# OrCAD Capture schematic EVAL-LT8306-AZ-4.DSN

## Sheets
1 P2 misc
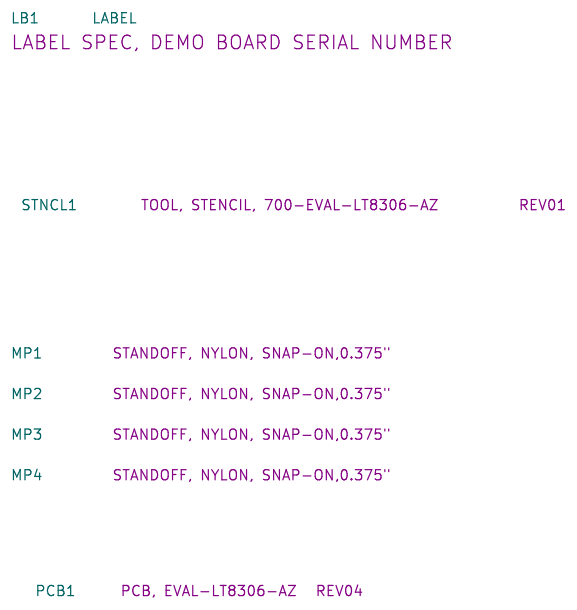
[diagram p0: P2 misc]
2 P1: size Custom; note: LOW-IQ NO-OPTO ISOLATED FLYBACK CONTROLLER
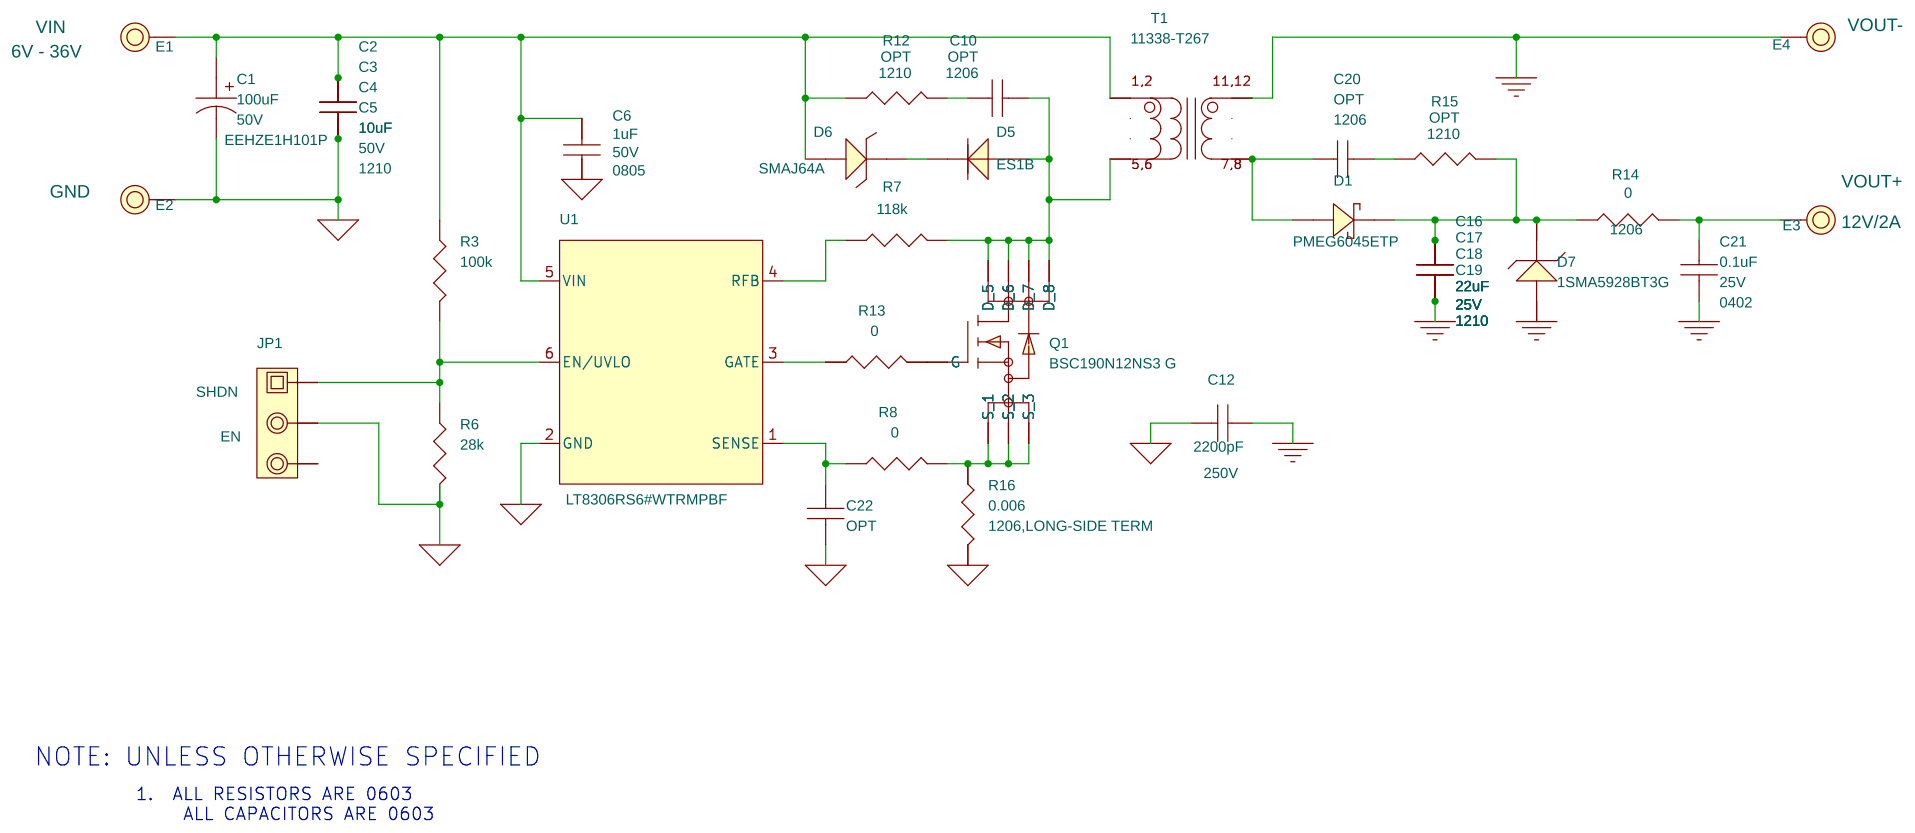
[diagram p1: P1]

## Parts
sheet P1
C1  100uF  [PANASONIC_ZE_10X10-2]
C2  10uF  [CC1210N]
C3  10uF  [CC1210N]
C4  10uF  [CC1210N]
C5  10uF  [CC1210N]
C6  1uF  [CC0805N]
C10  OPT  [CC1206N]
C12  2200pF  [CC1812N]
C16  22uF  [CC1210N]
C17  22uF  [CC1210N]
C18  22uF  [CC1210N]
C19  22uF  [CC1210N]
C20  OPT  [CC1206N]
C21  0.1uF  [CC0402N]
C22  OPT  [CC0603N]
D1  PMEG6045ETP  [SOD-128N]
D5  ES1B  [SMA-N]
D6  SMAJ64A  [SMA-N]
D7  1SMA5928BT3G  [SMA-N]
E1  TEST POINT  [MILLMAX2501]
E2  TEST POINT  [MILLMAX2501]
E3  TEST POINT  [MILLMAX2501]
E4  TEST POINT  [MILLMAX2501]
JP1  HDR  [HD1X3-079]
Q1  BSC190N12NS3 G  [INFINEON-PG-TDSON-8]
R3  100k  [CR0603N]
R6  28k  [CR0603N]
R7  118k  [CR0603N]
R8  0  [CR0603N]
R12  OPT  [CR1210N]
R13  0  [CR0603N]
R14  0  [CR1206N]
R15  OPT  [CR1210N]
R16  0.006  [SUSUMU-KRL3216]
T1  11338-T267  [SUMIDA-CEEH178]
U1  LT8306RS6#WTRMPBF  [LTC-S6-6-1636]
XJP1  SHUNT
sheet P2 misc
LB1  LABEL  [895-0154_REV01]
MP1  STANDOFF, NYLON, SNAP-ON  [KEYSTONE_8829-8834]
MP2  STANDOFF, NYLON, SNAP-ON  [KEYSTONE_8829-8834]
MP3  STANDOFF, NYLON, SNAP-ON  [KEYSTONE_8829-8834]
MP4  STANDOFF, NYLON, SNAP-ON  [KEYSTONE_8829-8834]
PCB1  PCB, EVAL-LT8306-AZ
STNCL1  TOOL, STENCIL, 700-EVAL-LT8306-AZ

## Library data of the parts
C1 = CAP_P_ALT: CAP.,100uF,ALUM POLY,50V,20%,10mmX10.2mm,AEC-Q200; CLASS: DISCRETE; Dielectric Type: ALUM POLY; Inventory Qty: 0; Manufacturer: PANASONIC; Manufacturer PN: EEHZE1H101P; PART_NUMBER: 150-0875; Package Size: 10mmX10.2mm; Rated Voltage: 50V; Tolerance: 20%
C2-C5 = CAP: CAP.,10uF,X5R,50V,10%,1210; CLASS: DISCRETE; Dielectric Type: X5R; FPLIST: CC1210N,CC1210L,CC1210M; Inventory Qty: 14956; Manufacturer: TDK; Manufacturer PN: C3225X5R1H106K250AB; PART_NUMBER: 150-3288; Package Size: 1210; Rated Voltage: 50V; Tolerance: 10%
C6 = CAP: CAP.,1uF,X7R,50V,10%,0805; CLASS: DISCRETE; Dielectric Type: X7R; FPLIST: CC0805N,CC0805L,CC0805M; Inventory Qty: 31167; Manufacturer: TAIYO YUDEN; Manufacturer PN: UMK212B7105KG-T; PART_NUMBER: 150-3335; Package Size: 0805; Rated Voltage: 50V; Tolerance: 10%
C10 C20 = CAP: CAP., OPTION, 1206; CLASS: DISCRETE; FPLIST: CC1206N,CC1206L,CC1206M; PART_NUMBER: 150-3160; Package Size: 1206; Package Type: SMD
C12 = CAP: CAP.,2200pF,X7R,250V,10%,1812; CLASS: DISCRETE; Dielectric Type: X7R; FPLIST: CC1812N,CC1812L,CC1812M; Inventory Qty: 6450; Manufacturer: MURATA; Manufacturer PN: GA343QR7GD222KW01L; PART_NUMBER: 150-0105; Package Size: 1812; Rated Voltage: 250V; Tolerance: 10%
C16-C19 = CAP: CAP.,22uF,X7R,25V,10%,1210; CLASS: DISCRETE; Dielectric Type: X7R; FPLIST: CC1210N,CC1210L,CC1210M; Inventory Qty: 28580; Manufacturer: AVX; Manufacturer PN: 12103C226KAT2A; PART_NUMBER: 150-3343; Package Size: 1210; Rated Voltage: 25V; Tolerance: 10%
C21 = CAP: CAP.,0.1uF,X7R,25V,10%,0402; CLASS: DISCRETE; Dielectric Type: X7R; FPLIST: CC0402N,CC0402L,CC0402M; Inventory Qty: 44848; Manufacturer: AVX; Manufacturer PN: 04023C104KAT2A; PART_NUMBER: 150-2276; Package Size: 0402; Rated Voltage: 25V; Tolerance: 10%
C22 = CAP: CAP., OPTION, 0603; CLASS: DISCRETE; FPLIST: CC0603N,CC0603L,CC0603M; PART_NUMBER: 150-3038; Package Size: 0603; Package Type: SMD
D1 = DIODE_SCHOTTKY_A_ALT: DIODE,SCHOTTKY,60V,4.5A,SOD-128,AEC-Q101; CLASS: DISCRETE; FPLIST: SOD-128N,SOD-128L,SOD-128M; Inventory Qty: 0; Manufacturer: NEXPERIA; Manufacturer PN: PMEG6045ETPX; Max Forward Current or Rated Power: 4.5A; PART_NUMBER: 210-0577; Package Size: SOD-128; Package Type: SOD-128; Rated Voltage or Zener Voltage: 60V
D5 = DIODE_A_ALT: DIODE,SWITCHING,100V,1A,2-pin SMA,AEC-Q101; CLASS: DISCRETE; Inventory Qty: 0; Manufacturer: VISHAY; Manufacturer PN: ES1BHE3_A/H; PART_NUMBER: 210-0523; Package Size: DO-214AC, SMA; Package Type: 2-pin SMA; Rated Voltage or Zener Voltage: 100V
D6 = DIODE_TVS_B_ALT: DIODE,TVS,UNI-DIRECT,64V,400W,SMA; CLASS: DISCRETE; FPLIST: SMA-N,SMA-L,SMA-M,SMA; Inventory Qty: 0; Manufacturer: LITTELFUSE; Max Forward Current or Rated Power: 400W; PART_NUMBER: 210-0578; Package Type: SMA; Rated Voltage or Zener Voltage: 64V
D7 = ZENER_ALT: DIODE,ZENER,13V,1.5W,SMA,AEC-Q101; CLASS: DISCRETE; FPLIST: SMA-N,SMA-L,SMA-M,SMA; Inventory Qty: 0; Manufacturer: ON SEMICONDUCTOR; PART_NUMBER: 210-0579; Package Size: SMA; Package Type: SMA; Rated Voltage or Zener Voltage: 13V
E1 = TESTPOINT_.219_MILL-MAX_2501: TEST POINT,TURRET,0.094" MTG. HOLE,PCB 0.062" THK; CLASS: IO; Inventory Qty: 823526; Manufacturer: MILL-MAX; Manufacturer PN: 2501-2-00-80-00-00-07-0; PART_FIELD_01: VIN; PART_FIELD_02: 6V - 36V; PART_NUMBER: 260-0003
E2 = TESTPOINT_.219_MILL-MAX_2501: TEST POINT,TURRET,0.094" MTG. HOLE,PCB 0.062" THK; CLASS: IO; Inventory Qty: 823526; Manufacturer: MILL-MAX; Manufacturer PN: 2501-2-00-80-00-00-07-0; PART_FIELD_01: GND; PART_NUMBER: 260-0003
E3 = TESTPOINT_.219_MILL-MAX_2501: TEST POINT,TURRET,0.094" MTG. HOLE,PCB 0.062" THK; CLASS: IO; Inventory Qty: 823526; Manufacturer: MILL-MAX; Manufacturer PN: 2501-2-00-80-00-00-07-0; PART_FIELD_01: VOUT+; PART_FIELD_02: 12V/2A; PART_NUMBER: 260-0003
E4 = TESTPOINT_.219_MILL-MAX_2501: TEST POINT,TURRET,0.094" MTG. HOLE,PCB 0.062" THK; CLASS: IO; Inventory Qty: 823526; Manufacturer: MILL-MAX; Manufacturer PN: 2501-2-00-80-00-00-07-0; PART_FIELD_01: VOUT-; PART_FIELD_02: 12V/4A, VIN>12V; PART_NUMBER: 260-0003
JP1 = 1X3_A: CONN.,HDR,MALE,1x3,2mm,VERT,ST,THT,NO SUBS. ALLOWED; 10th Part Field: EN; 12th Part Field: SHDN; 9th Part Field: SHDN; CLASS: IO; Inventory Qty: 28997; Manufacturer: Wurth Elektronik; Manufacturer PN: 62000311121; PART_NUMBER: 250-0639
Q1 = 8P_N-CH_TYPE1A: XSTR.,MOSFET,N-CH,120V,8.6A,TDSON-8; CLASS: DISCRETE; Inventory Qty: 12900; Manufacturer: INFINEON; PART_NUMBER: 240-0022; Package Type: TDSON-8; Rated Voltage: 120V
R3 = RES: RES.,100k OHMS,1%,1/10W,0603,AEC-Q200; CLASS: DISCRETE; FPLIST: CR0603N,CR0603L,CR0603M; Inventory Qty: 185604; Manufacturer: VISHAY; Manufacturer PN: CRCW0603100KFKEA; PART_NUMBER: 100-0343; Package Size: 0603; Rated Power: 1/10W; Temperature Coefficient: +/-100ppm; Tolerance: 1%
R6 = RES: RES.,28k OHMS,1%,1/10W,0603,AEC-Q200; CLASS: DISCRETE; FPLIST: CR0603N,CR0603L,CR0603M; Inventory Qty: 24672; Manufacturer: PANASONIC; Manufacturer PN: ERJ3EKF2802V; PART_NUMBER: 100-0094; Package Size: 0603; Rated Power: 1/10W; Temperature Coefficient: 100ppm/C; Tolerance: 1%
R7 = RES: RES.,118k OHMS,1%,1/10W,0603,AEC-Q200; CLASS: DISCRETE; FPLIST: CR0603N,CR0603L,CR0603M; Inventory Qty: 34758; Manufacturer: VISHAY; Manufacturer PN: CRCW0603118KFKEA; PART_NUMBER: 100-0667; Package Size: 0603; Rated Power: 1/10W; Temperature Coefficient: 100ppm; Tolerance: 1%
R8 R13 = RES: RES.,0 OHM,1/10W,0603,AEC-Q200; CLASS: DISCRETE; FPLIST: CR0603N,CR0603L,CR0603M; Inventory Qty: 676258; Manufacturer: VISHAY; Manufacturer PN: CRCW06030000Z0EA; PART_NUMBER: 100-0009; Package Size: 0603; Rated Power: 1/10W
R12 R15 = RES: RES., OPTION, 1210; CLASS: DISCRETE; FPLIST: CR1210N,CR1210L,CR1210M; PART_NUMBER: 100-0100; Package Size: 1210
R14 = RES: RES.,0 OHM,1/4W,1206,AEC-Q200; CLASS: DISCRETE; FPLIST: CR1206N,CR1206L,CR1206M; Inventory Qty: 36327; Manufacturer: VISHAY; Manufacturer PN: CRCW12060000Z0EA; PART_NUMBER: 100-0200; Package Size: 1206; Rated Power: 1/4W
R16 = RES: RES.,0.006 OHM,1%,1.5W,1206,LONG-SIDE TERM,METAL,SENSE,AEC-Q200; CLASS: DISCRETE; Inventory Qty: 3332; Manufacturer: SUSUMU; Manufacturer PN: KRL3216E-C-R006-F-T1; PART_NUMBER: 100-0513; Package Size: 1206,LONG-SIDE TERM; Rated Power: 1.5W; Temperature Coefficient: 50ppm; Tolerance: 1%
T1 = SUMIDA-CEEH178-11338-T267: TRANSFORMER,1:1,Np: 6-36Vin, Ns: 12V with 2A,19x17mm SMD,CEEH178 CUSTOM; CLASS: DISCRETE; Inventory Qty: 0; Manufacturer: SUMIDA; Manufacturer PN: 11338-T267 (CEEH178); PART_NUMBER: 410-0142; Turns Ratio: 1:1
U1 = LT8306-S6: IC,FLYBACK CONVERTER,6-pin SOT-23; CLASS: IC; Inventory Qty: 0; Manufacturer: ANALOG DEVICES; Package Type: 6-pin SOT-23
XJP1 = SHUNT_2MM_C: CONN.,SHUNT,FEMALE,2-POS,2mm; CLASS: IO; Inventory Qty: 64675; Manufacturer: Wurth Elektronik; Manufacturer PN: 60800213421; PART_NUMBER: 250-0485
LB1 = BLANK_LABEL: LABEL SPEC, DEMO BOARD SERIAL NUMBER; Inventory Qty: 0; Manufacturer: BRADY; Manufacturer PN: THT-96-717-10; PART_NUMBER: 895-0154
MP1-MP4 = BLANK_PINLESS_MECHANICAL_PART: STANDOFF, NYLON, SNAP-ON,0.375"; CLASS: DISCRETE; FPLIST: KEYSTONE_8829-8834,KEYSTONE_8832; Inventory Qty: 202920; Manufacturer: KEYSTONE; Manufacturer PN: 8832; PART_NUMBER: 763-0008
PCB1 = BLANK_PCB_PART: BOM Notes: REV04; CLASS: DISCRETE; Inventory Qty: 0; PART_NUMBER: TMP-8206
STNCL1 = BLANK_STENCIL_PART: BOM Notes: REV01; CLASS: DISCRETE; Inventory Qty: 0; PART_NUMBER: TMP-8209

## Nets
DGND: C12.1 C16.2 C17.2 C18.2 C19.2 C21.2 D7.2(A) E4.1 T1.11 T1.12
GND: C1.2 C2.2 C3.2 C4.2 C5.2 C6.1 C12.2 C22.2 E2.1 JP1.2 R6.2 R16.2 U1.2(GND)
NC3: T1.3(NC3)
NC4: T1.4(NC4)
NC9: T1.9(NC9)
NC10: T1.10(NC10)
N02582: JP1.1 R3.2 R6.1 U1.6(EN/UVLO)
N02598: C1.1 C2.1 C3.1 C4.1 C5.1 C6.2 D6.2(A) E1.1 R3.1 R12.1 T1.1 T1.2 U1.5(VIN)
N16800300: C16.1 C17.1 C18.1 C19.1 D1.1(C) D7.1(C) R14.1 R15.2
N16861531: C20.1 D1.2(A) T1.7 T1.8
N16889692: R7.1 U1.4(RFB)
N16889710: R13.1 U1.3(GATE)
N16889866: C22.1 R8.1 U1.1(SENSE)
N16889921: Q1.1(S) Q1.2(S) Q1.3(S) R8.2 R16.1
N16890067: C10.2 D5.2(A) Q1.5(D) Q1.6(D) Q1.7(D) Q1.8(D) R7.2 T1.5 T1.6
N16891039: D5.1(C) D6.1(C)
N16891397: C10.1 R12.2
N16904434: C20.2 R15.1
N16905272: C21.1 E3.1 R14.2
N16919439: Q1.4(G) R13.2

Not connected (* = marked no-connect by the designer): JP1 3

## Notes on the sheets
sheet 2
- NOTE: UNLESS OTHERWISE SPECIFIED
- 1.  ALL RESISTORS ARE 0603
       ALL CAPACITORS ARE 0603
